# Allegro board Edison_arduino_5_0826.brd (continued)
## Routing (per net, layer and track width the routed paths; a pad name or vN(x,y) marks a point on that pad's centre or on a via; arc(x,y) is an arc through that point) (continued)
VBUS: length 8.6
  TOP w0.203: 20.96,17.02 21.3,16.67 J7.20
  TOP w0.3: Q10.3 103.02,18.64 ; Q10.2 103.02,19.59 ; CR1.2 v1(108.23,41.81)
  BOTTOM w0.3: TP18.1 16.83,20 v1(16.76,20.07)
  vias: v1(16.76,20.83) v1(114.45,16.66) v1(114.45,15.71)
VBUS_2: length 11.6
  TOP w0.3: R8.1 C9.2 110.49,9.01 110.76,8.74 U2.19
  TOP w0.33: 111.65,9.64 R8.1
  TOP w0.381: 117.49,5.24 116.41,5.22 115.22,6.41 115.22,8.53 114.11,9.64 111.65,9.64
VBUS_IN: length 5.9
  TOP w0.127: 108.74,20.09 108.12,20.09 R96.1 108.1,19.08
  TOP w0.381: CR8.2 113.98,19.2 ; CR8.2 113.18,18.58 ; CR8.2 112.38,19.2 ; J16.1 116.49,19.19 116.48,19.2
  TOP w0.5: 107.84,18.63 107.83,18.64 Q10.4
VBUS_OUT: length 3.9
  TOP w0.127: J6.1 C36.1 v1(111.03,44.22)
  TOP w0.25: U36.1 25.13,36.9 v1(24.92,37.11)
VIN: length 3.9
  PWR_GND w0.381: 73.63,60.12 J2A1.8 ; J2A1.8 74.6,59.16 ; J2A1.8 74.6,61.09 ; J2A1.8 75.57,60.12
  vias: v1(96.03,61.22) v1(96.05,60.35) v1(96.03,59.36) v1(96.05,58.46)
A0: length 55.7
  TOP w0.127: R52.2 61.35,46 62.36,47.01 62.36,54.74 66.19,58.57 67.97,58.57 J1A1.1 ; U15.A1 v1(62.5,40.76)
  BOTTOM w0.127: J1A1.1 69.22,60.43 TP64.1 70.87,63.12 70.87,51.74 71.02,51.59 71.02,49.81 70.13,48.92 69.24,48.92 68.2,47.88 64.49,47.88 61.75,45.14 61.75,43.91 62.5,43.16 v1(62.5,40.76)
A1: length 55.2
  TOP w0.127: J1A1.2 61.72,54.86 61.72,47.18 61.29,46.75 R53.2 ; U13.A1 v1(64.75,40.75)
  BOTTOM w0.127: J1A1.2 66.67,60.43 TP65.1 67.35,65.44 69.73,65.44 71.42,63.74 71.42,49.71 70.26,48.54 69.47,48.54 68.12,47.19 65.76,47.19 63.98,45.42 63.98,43.84 64.75,43.07 v1(64.75,40.75)
A2: length 55.4
  TOP w0.127: J1A1.3 61.03,56.72 R54.2 ; U11.A1 v1(67,40.76)
  BOTTOM w0.127: v1(67,40.76) 67,43.44 65.99,44.45 65.99,46 66.57,46.58 68.78,46.58 71.86,49.66 71.86,63.79 69.92,65.73 65.09,65.73 TP66.1 64.13,60.43 J1A1.3
A3: length 53.9
  TOP w0.127: R55.2 60.49,52.52 60.49,58.71 J1A1.4 ; U9.A1 v1(69.25,40.76)
  BOTTOM w0.127: J1A1.4 61.59,60.43 TP67.1 62.88,66.05 70.1,66.05 72.34,63.81 72.34,49.3 69.04,46 69.04,45.39 68.4,44.75 68.4,44.02 69.25,43.17 v1(69.25,40.76)
A4: length 106.7
  TOP w0.127: v1(72.75,34.29) 73.38,33.66 76.58,33.66 78.36,35.43 87.38,35.43 88.39,34.42 88.39,30.28 98.98,19.69 J2B1.9 ; R56.2 57.5,50.85 59.36,52.7 J1A1.5 ; U7.A1 v1(71.5,40.76)
  BOTTOM w0.127: J1A1.5 59.05,60.43 TP68.1 60.62,66.34 70.3,66.34 72.87,63.76 72.87,46.86 70.66,44.65 70.66,44.22 71.5,43.38 v1(71.5,40.76) 71.5,39.73 72.52,38.71 72.52,34.52 v1(72.75,34.29)
A5: length 109.3
  TOP w0.127: U5.A1 v1(73.75,40.76) ; v1(75.01,34.29) 76.53,35.81 87.53,35.81 88.77,34.57 88.77,30.53 101.52,17.78 J2B1.10 ; R57.2 56.75,51.16 58.42,52.83 58.42,58.52 J1A1.6
  BOTTOM w0.127: v1(75.01,34.29) 75.01,38.22 73.75,39.48 v1(73.75,40.76) 73.75,43.17 72.97,43.94 72.97,44.75 74.09,45.87 74.09,56.67 73.36,57.4 73.36,63.74 70.43,66.67 58.41,66.67 TP69.1 56.52,60.43 J1A1.6
AIN0: length 50
  TOP w0.127: U15.C2 63.63,38.62 63.63,37.47 64.9,36.2 87.63,36.2 89.15,34.67 89.15,30.77 90.93,29 99,29 100.71,30.71 100.71,34.29 100.53,34.47 R74.2
AIN1: length 43.6
  TOP w0.127: U13.C2 65.79,38.71 65.79,37.34 66.55,36.58 87.88,36.58 89.64,34.83 89.64,30.87 91.25,29.25 98,29.25 99.5,30.75 R75.2
AIN2: length 39.4
  TOP w0.127: R76.2 98,30.5 97.25,29.75 91.46,29.75 90.14,31.07 90.14,34.82 88,36.96 68.58,36.96 68.07,37.47 68.07,38.68 U11.C2
AIN3: length 35
  TOP w0.127: U9.C2 70.23,38.77 70.23,37.72 70.59,37.37 88.3,37.37 90.64,35.03 90.64,31.28 91.66,30.25 96,30.25 96.5,30.75 R77.2
AIN4: length 30.2
  TOP w0.127: U7.C2 72.52,38.73 72.52,38.23 73.03,37.72 88.65,37.72 91.14,35.24 91.14,31.49 91.87,30.75 94.5,30.75 95,31.25 R78.2
AIN5: length 25.4
  TOP w0.127: R79.2 93.5,31.5 93.25,31.25 92.32,31.25 91.64,31.94 91.64,35.44 88.6,38.48 76.27,38.48 75.5,39.25 U5.C2
AREF: length 67.7
  BOTTOM w0.127: J8.3 89.82,51.15 89.82,46.05 91.2,44.67 91.2,40.55 91.47,40.29 92.61,40.29 93.88,41.56 97.82,41.56 97.94,41.68 102.84,41.68 104.49,40.03 105.6,40.03 110.28,35.36 110.28,32.05 107.85,29.62 105.92,29.62 105.03,28.73 105.03,24 96.44,15.42 J2B1.8
DIG0: length 37.8
  TOP w0.127: J1B1.1 56.82,11.86 56.82,14.56 v1(57.09,14.83) 56.82,15.1 U33.C2 ; R64.2 76.84,26.75 v1(76.84,26.75)
  BOTTOM w0.127: J1B1.1 56.77,11.81 TP70.1 ; v1(57.09,14.83) 57.79,15.53 57.79,17.48 59.98,19.69 65.2,19.69 65.3,19.59 72.96,19.59 74.7,21.33 74.7,24.62 v1(76.84,26.75)
DIG1: length 34.8
  TOP w0.127: U31.C2 59.36,15.1 v1(59.63,14.83) 59.36,14.56 59.36,11.86 J1B1.2 ; R65.2 v1(77.35,26)
  BOTTOM w0.127: v1(59.63,14.83) 60.33,15.53 60.33,17.43 62.2,19.3 73.22,19.3 75.06,21.14 75.06,24.38 76.67,26 v1(77.35,26) ; J1B1.2 59.31,11.81 TP71.1
DIG2: length 31.8
  TOP w0.127: U29.C2 61.9,15.1 v1(62.17,14.83) 61.9,14.56 61.9,11.86 J1B1.3 ; R66.2 76.84,25.25 v1(76.84,25.25)
  BOTTOM w0.127: J1B1.3 61.85,11.81 TP72.1 ; v1(62.17,14.83) 62.87,15.53 62.87,17.65 64.13,18.92 73.38,18.92 75.44,20.99 75.44,23.85 v1(76.84,25.25)
DIG3: length 29.1
  TOP w0.127: U27.C2 64.44,15.1 v1(64.71,14.83) 64.44,14.56 64.44,11.86 J1B1.4 ; R67.2 v1(77.35,24.5)
  BOTTOM w0.127: v1(77.35,24.5) 76.7,24.5 75.82,23.62 75.82,20.83 73.53,18.54 66.04,18.54 65.28,17.78 65.28,15.4 v1(64.71,14.83) ; J1B1.4 64.52,11.79 TP73.1
DIG4: length 26
  TOP w0.127: U24.C2 66.98,15.1 v1(67.25,14.83) 66.98,14.56 66.98,11.86 J1B1.5 ; R68.2 76.84,23.75 v1(76.84,23.75)
  BOTTOM w0.127: v1(76.84,23.75) 76.84,20.7 74.3,18.16 68.83,18.16 67.94,17.27 67.94,15.53 v1(67.25,14.83) ; TP74.1 67.06,11.79 J1B1.5
DIG5: length 22.8
  TOP w0.127: R69.2 v1(77.35,23) ; U21.C2 69.52,15.1 v1(69.79,14.83) 69.52,14.56 69.52,11.86 J1B1.6
  BOTTOM w0.127: J1B1.6 69.6,11.79 TP75.1 ; v1(77.35,23) 77.35,20.71 74.42,17.78 70.87,17.78 70.36,17.27 70.36,15.4 v1(69.79,14.83)
DIG6: length 9.4
  TOP w0.127: J1B1.7 72.06,11.86 U19.C2 72.07,15.54 R70.2
  BOTTOM w0.127: TP76.1 72.01,11.81 J1B1.7
DIG7: length 9.6
  TOP w0.127: R71.2 75.53,15.53 U32.C2 74.6,11.86 J1B1.8
  BOTTOM w0.127: J1B1.8 74.55,11.81 TP77.1
DIG8: length 16.4
  TOP w0.127: J2B1.1 78.66,11.86 78.66,14.56 v1(78.93,14.83) 78.66,15.1 U30.C2 ; R58.2 82.5,20.52 v1(82.3,20.32)
  BOTTOM w0.127: v1(82.3,20.32) 79.63,17.65 79.63,15.53 v1(78.93,14.83) ; J2B1.1 78.61,11.81 TP78.1
DIG9: length 15.7
  TOP w0.127: R59.2 v1(83.25,20.35) ; U28.C2 81.2,15.1 v1(81.47,14.83) 81.2,14.56 81.2,11.86 J2B1.2
  BOTTOM w0.127: TP79.1 81.28,11.79 J2B1.2 ; v1(81.47,14.83) 82.04,15.4 82.04,19.14 v1(83.25,20.35)
DIG10: length 15.4
  TOP w0.127: J2B1.3 83.74,11.86 83.74,14.56 v1(84.01,14.83) 83.74,15.1 U26.C2 ; R60.2 84,20.52 v1(84.2,20.32)
  BOTTOM w0.127: v1(84.01,14.83) 84.58,15.4 84.58,19.94 v1(84.2,20.32) ; J2B1.3 83.82,11.79 TP80.1
DIG11: length 66.4
  TOP w0.127: R61.2 86.86,23.25 v1(87,23.11) 87,22.35 84.48,19.84 81.69,19.84 79.02,22.51 76.55,22.51 74.42,24.64 74.42,28.15 72.7,29.87 62.64,29.87 59.97,32.54 58.57,32.54 57.59,33.53 55.35,33.53 J4.4 ; U23.C2 86.28,15.1 v1(86.55,14.83) 86.28,14.56 86.28,11.86 J2B1.4
  BOTTOM w0.127: TP81.1 86.23,11.81 J2B1.4 ; v1(86.55,14.83) 86.55,15.56 87.15,16.16 87.15,17.05 88.42,18.32 88.42,18.57 88.8,18.95 90.58,18.95 90.96,19.33 90.96,21.24 89.08,23.11 v1(87,23.11)
DIG12: length 65.1
  TOP w0.127: U20.C2 88.82,15.1 v1(89.09,14.83) 88.82,14.56 88.82,11.86 J2B1.5 ; R62.2 v1(86.9,24) 87.12,24 87.63,23.5 87.63,22.61 84.61,19.59 81.56,19.59 78.89,22.25 76.17,22.25 73.91,24.51 73.91,27.81 72.14,29.59 62.54,29.59 59.95,32.18 J4.1
  BOTTOM w0.127: v1(86.9,24) 89.59,24 92.36,21.24 92.36,20.22 90.96,18.82 90.96,18.19 90.58,17.81 90.32,17.81 89.94,17.43 89.94,16.28 89.09,15.43 v1(89.09,14.83) ; J2B1.5 88.77,11.81 TP82.1
DIG13: length 67.6
  TOP w0.127: U18.C2 91.36,15.1 v1(91.63,14.83) 91.36,14.56 91.36,11.86 J2B1.6 ; R63.2 86.73,24.75 v1(86.87,24.89) 87.25,24.89 88.01,24.13 88.01,22.61 84.74,19.33 81.43,19.33 78.77,22 75.79,22 73.41,24.38 73.41,27.18 71.35,29.24 62.18,29.24 v1(59.8,31.61)
  BOTTOM w0.127: v1(59.8,31.61) J4.3 ; v1(86.87,24.89) 86.97,24.79 89.69,24.79 92.74,21.74 92.74,17.05 91.63,15.94 v1(91.63,14.83) ; J2B1.6 91.31,11.81 TP83.1
DIG13_1P8: length 65.8
  TOP w0.127: U43.A1 91.46,18.45 v1(91.47,18.44) 91.09,18.06 87.66,18.06 86.64,19.08 81.31,19.08 78.64,21.74 75.47,21.74 73.05,24.16 73.05,26.82 70.89,28.98 60.48,28.98 54.89,23.4 46.89,23.4 45.12,25.17 R87.1 ; U18.C1 90.33,15.53 v1(90.07,15.27)
  TOP w0.2: Q9.1 R87.1
  BOTTOM w0.127: v1(91.47,18.44) 91.47,18.32 90.96,17.81 90.96,15.9 90.32,15.27 v1(90.07,15.27)
FAULT: length 39.9
  TOP w0.127: J7.19 21.3,10 20.77,9.47 R36.1 20.14,9.47 20.02,9.34 20.02,8.48 v1(20.5,8) ; U36.3 25.82,32.93 v1(22.48,29.59)
  BOTTOM w0.127: v1(22.48,29.59) 14.82,21.94 14.82,17.9 15.94,16.79 15.94,13.94 20.5,9.38 20.5,8 v1(20.5,8) TP19.1
FW_RCVR: length 127
  TOP w0.127: SW1UI3.1 8.41,66.82 v1(8.41,65.81) ; v1(34,8) 32.98,9.02 32.51,9.02 31.3,10.23 J7.69
  BOTTOM w0.127: TP63.1 v1(34,8) 36,8 36.6,7.39 38.38,7.39 38.63,7.65 38.63,10.44 38.13,10.95 36.86,10.95 36.29,10.38 33.75,10.38 30.88,13.25 18.59,13.25 17.27,14.57 17.27,18.22 16.04,19.45 16.04,20.87 22,26.82 26.32,26.82 27.97,28.48 27.97,29.62 26.95,30.63 4.73,30.63 3.84,31.52 3.84,53.88 5.36,55.4 7.9,55.4 9.81,57.3 9.81,60.35 8.41,61.75 v1(8.41,65.81)
GP12_PWM0: length 43.7
  TOP w0.127: v1(32.64,9.78) 33.53,9.78 33.73,9.98 34.72,9.98 35.43,9.27 38.61,9.27 42.45,13.11 42.45,14.25 43.51,15.32 44.53,15.32 45.16,15.95 45.16,18.08 J12.2 ; J7.35 24.5,4 v1(23.5,3)
  BOTTOM w0.127: v1(32.64,9.78) 27.56,9.78 25.78,8 25.78,6.48 25.53,6.22 25.02,6.22 24.26,5.46 24.26,3.76 v1(23.5,3) TP34.1
GP13_PWM1: length 36.8
  TOP w0.127: J7.33 24.1,8.1 24,8 24,6 v1(23.5,5.5) ; J11.2 43.79,16.23 42.06,14.51 42.06,13.24 38.63,9.81 v1(36.73,9.81)
  BOTTOM w0.127: TP32.1 v1(23.5,5.5) 23.79,5.5 24.38,6.1 24.38,10.41 25.27,11.3 32.46,11.3 33.7,10.06 36.48,10.06 v1(36.73,9.81)
GP14: length 77.4
  TOP w0.127: J7.48 26.9,15.39 26.48,15.81 26.48,16.83 26,17.31 v1(26,19) ; U6.C1 72,44.21 v1(72.25,44.45)
  BOTTOM w0.127: v1(72.25,44.45) 72.07,44.28 72.07,41.33 72.25,41.15 72.25,40.28 73.6,38.93 73.6,33.59 73.18,33.17 71.91,33.17 68.23,29.49 61.24,29.49 56.29,24.54 44.1,24.54 41.43,21.87 34.19,21.87 33.55,22.51 33.55,23.52 32.79,24.28 25.94,24.28 25.17,23.52 25.17,20.98 26,20.16 TP41.1 v1(26,19)
GP15: length 79.2
  TOP w0.127: v1(27.55,46.85) 27.55,39.5 29.75,37.3 29.75,30.15 28.65,29.05 28.65,25.65 25.25,22.25 25.25,15.35 25.7,14.9 J7.42 ; v1(59.7,44.78) 59.7,44.7 59.8,44.7 59.8,44.8 60.55,44.8 63.6,47.85 63.65,47.85 R122.1 ; v1(54.3,44.4) 52.55,44.4 v1(52.25,44.7) 52.95,44.7 54.25,46 U17.22
  BOTTOM w0.127: v1(52.25,44.7) 50.9,46.05 TP88.1 32.25,46.05 31.45,46.85 v1(27.55,46.85) ; v1(54.3,44.4) 54.35,44.4 54.75,44.8 59.8,44.8 59.8,44.7 59.7,44.7 v1(59.7,44.78)
GP19: length 171.4
  TOP w0.127: R44.1 64.83,51.75 v1(64.9,51.82) 64.9,51.72 65.11,51.5 U16.19 ; J7.41 25.7,8.97 26.06,8.62 26.06,3.44 v1(26.5,3) 27.82,1.68 88.93,1.68 95.4,8.16 95.4,22.76 88.01,30.15 88.01,32.26 87.5,32.77 85.72,32.77 85.47,33.02 85.47,34.8 85.47,34.8 v1(85.47,34.93) ; v1(75.56,54.61) v1(69.85,54.61) ; v1(69.85,27.94) 69.47,27.56 68.96,27.56 68.75,27.35 U34.19
  BOTTOM w0.127: v1(69.85,27.94) 72.42,30.51 77.62,30.51 81.28,34.16 84.71,34.16 v1(85.47,34.93) 85.47,40.34 83.67,42.14 83.67,45.49 75.56,53.59 v1(75.56,54.61) ; v1(69.85,54.61) 68.45,54.61 65.66,51.82 v1(64.9,51.82) ; TP37.1 v1(26.5,3)
GP20: length 169.8
  TOP w0.127: v1(74.93,53.34) 74.04,54.23 70.74,54.23 v1(69.85,53.34) ; v1(68.71,27.94) 68.25,27.48 U34.20 ; U16.20 64.97,51 v1(64.9,50.93) 64.82,51 R43.1 ; J7.43 26.1,9.21 27,8.31 27,6 v1(26.5,5.5) 26.5,3.73 28.17,2.06 88.55,2.06 95.02,8.54 95.02,14.51 94.52,15.01 94.52,19.33 92.99,20.86 92.99,24.54 88.8,28.73 88.8,28.86 88.42,29.24 88.29,29.24 87.5,30.03 87.5,32 87.12,32.39 81.28,32.39 80.97,32.7 80.97,34.8 80.97,34.8 v1(80.97,34.93)
  BOTTOM w0.127: TP38.1 v1(26.5,5.5) ; v1(64.9,50.93) 65.53,50.93 68.35,53.75 69.44,53.75 v1(69.85,53.34) ; v1(68.71,27.94) 71.78,31.02 77.36,31.02 80.97,34.63 v1(80.97,34.93) 83.19,37.14 83.19,45.09 v1(74.93,53.34)
GP27: length 121.9
  TOP w0.127: v1(38.48,11.94) 38.48,24.51 v1(39.88,25.91) ; v1(28,3) 27.43,3.57 27.43,8.51 26.5,9.44 J7.45 ; Q3.2 77.5,51.03 R39.1 76.86,53.64 76.86,56.08 71.35,61.59 53.63,61.59 50.91,58.88 50.91,58.11 v1(51.36,57.66)
  BOTTOM w0.127: TP40.1 v1(28,3) 28.7,3.7 28.7,5.46 29.21,5.97 34.42,5.97 35.31,5.08 36.7,5.08 38.89,7.27 38.89,11.53 v1(38.48,11.94) ; v1(51.36,57.66) 50.4,56.7 50.4,52.6 51.56,51.44 51.56,46.54 53.85,44.25 53.85,44.2 53.85,44.2 53.85,43.6 53.95,43.5 53.95,42.9 53.85,42.8 53.85,40.6 53.85,40.6 53.85,40.48 51.56,38.19 51.56,33.2 45.44,27.08 41.05,27.08 v1(39.88,25.91)
GP28: length 113.1
  TOP w0.127: v1(51.52,58.62) 53.99,61.09 71.04,61.09 76.2,55.93 76.2,53.39 75.51,52.7 74.8,52.7 73.91,53.59 72.77,53.59 72.5,53.32 R40.1 72.5,51.03 Q4.2 ; v1(37.85,10.31) 37.85,24.89 v1(38.86,25.91) ; v1(28,8) 28,8.83 26.9,9.93 J7.47
  BOTTOM w0.127: v1(37.85,10.31) 37.85,9.65 37.24,9.04 29.04,9.04 v1(28,8) TP42.1 ; v1(38.86,25.91) 40.39,27.43 45.01,27.43 51.05,33.48 51.05,38.22 53.56,40.72 53.56,42.91 53.65,43 53.65,43.4 53.56,43.49 53.56,44.09 51.05,46.6 51.05,51.45 49.9,52.6 49.9,57.4 51.12,58.62 v1(51.52,58.62)
GP40: length 80.4
  TOP w0.127: J7.52 27.7,16.3 v1(27.5,16.5) ; v1(90.2,19.46) 90.45,19.72 U43.B2
  BOTTOM w0.127: TP44.1 v1(27.5,16.5) 28.1,15.9 32.03,15.9 33.3,17.17 38.76,17.17 45.11,23.52 56.67,23.52 59.84,20.35 64.92,20.35 65.43,19.84 72.67,19.84 74.45,21.62 74.45,25.05 76.61,27.21 77.24,27.21 81.69,22.76 83.34,22.76 87.15,18.95 87.53,18.95 88.04,19.46 v1(90.2,19.46)
GP41: length 106.3
  TOP w0.127: v1(95.28,27.84) 95.28,25.3 96.29,24.28 105.44,24.28 108.48,27.33 108.48,31.14 107.47,32.15 U40.B2 ; v1(27.5,19) 28.1,18.4 J7.54
  BOTTOM w0.127: v1(95.28,27.84) 87.91,27.84 85.88,25.81 83.97,25.81 82.83,26.95 80.93,26.95 80.04,27.84 76.48,27.84 73.81,25.17 73.81,22.12 73.05,21.36 60.86,21.36 58.19,24.03 44.6,24.03 41.22,20.65 27.76,20.65 27.5,20.39 TP46.1 v1(27.5,19)
GP42: length 85.6
  TOP w0.127: v1(26,21.5) 26.8,20.7 26.8,16 27.3,15.5 J7.50 ; v1(87.28,19.46) 87.78,19.46 88.04,19.72 U42.B2
  BOTTOM w0.127: TP43.1 v1(26,21.5) 26.57,20.93 26.57,18.69 27.08,18.19 39.4,18.19 44.98,23.78 57.56,23.78 60.48,20.86 73.31,20.86 74.2,21.74 74.2,25.17 76.48,27.46 77.37,27.46 81.81,23.01 83.72,23.01 v1(87.28,19.46)
GP43: length 109.1
  TOP w0.127: v1(29,19) 28.5,18.5 J7.56 ; v1(107.6,35.33) 107.47,35.2 U41.B2
  BOTTOM w0.127: TP48.1 v1(29,19) 28.91,19 28.35,18.44 27.33,18.44 26.93,18.85 26.93,20.63 27.33,21.03 41.1,21.03 44.35,24.28 58.7,24.28 61.24,21.74 72.67,21.74 73.31,22.38 73.31,25.05 80.93,32.67 89.31,32.67 91.72,35.08 91.72,39.14 92.1,39.52 97.44,39.52 97.69,39.27 101.37,39.27 102.26,38.38 106.67,38.38 108.21,36.84 108.21,35.94 v1(107.6,35.33)
GP44: length 71.8
  TOP w0.127: U14.C1 63,44.21 v1(63.25,44.45) ; v1(21.84,19.18) 22.1,18.92 J7.24
  BOTTOM w0.127: v1(63.25,44.45) 63.07,44.28 63.07,41.33 63.25,41.15 63.25,40.28 64.6,38.93 64.6,32.47 62.99,30.86 50.19,30.86 45.97,26.64 44.68,26.64 42.95,24.92 38.38,24.92 36.73,26.57 24.23,26.57 20.9,23.24 20.9,21.77 21.46,21.21 21.46,20.04 TP22.1 21.5,19.52 v1(21.84,19.18)
GP45: length 73.7
  TOP w0.127: v1(22.48,22.48) 22.48,20.52 22.5,20.5 J7.26 ; U12.C1 65.25,44.21 v1(65.5,44.45)
  BOTTOM w0.127: v1(22.48,22.48) 22.46,22.5 TP24.1 21.5,23.15 24.54,26.19 33.81,26.19 35.49,24.51 42.93,24.51 43.72,25.3 46.38,25.3 51.56,30.48 64.56,30.48 66.85,32.77 66.85,38.93 65.5,40.28 65.5,41.15 65.32,41.33 65.32,44.28 v1(65.5,44.45)
GP46: length 74.5
  TOP w0.127: v1(67.75,44.45) 67.5,44.21 U10.C1 ; J7.28 22.9,16.4 v1(23,16.5)
  BOTTOM w0.127: v1(67.75,44.45) 67.57,44.28 67.57,41.33 67.75,41.15 67.75,40.28 69.1,38.93 69.1,33.02 66.2,30.13 51.72,30.13 46.64,25.05 43.84,25.05 42.85,24.05 35.44,24.05 33.55,25.94 25.05,25.94 23.49,24.38 23.49,21.59 22.35,20.45 22.35,18.15 TP26.1 v1(23,16.5)
GP47: length 76.2
  TOP w0.127: v1(70,44.45) 69.75,44.21 U8.C1 ; J7.30 23.3,15.93 23.5,16.13 23.5,18.51 v1(23,19)
  BOTTOM w0.127: v1(70,44.45) 69.82,44.28 69.82,41.33 70,41.15 70,40.28 71.35,38.93 71.35,33.14 68.07,29.87 61.11,29.87 56.03,24.79 43.97,24.79 42.88,23.7 35.28,23.7 33.3,25.68 25.3,25.68 23.88,24.26 23.88,21.58 23,20.7 TP28.1 v1(23,19)
GP48: length 60.9
  TOP w0.127: J7.32 23.7,15.7 23.88,15.88 23.88,18.38 v1(24.5,19) ; v1(73.85,14.83) 74.09,15.07 U32.C1
  BOTTOM w0.127: TP29.1 v1(24.5,19) 25.27,18.23 25.27,16.51 26.54,15.24 33.15,15.24 33.81,15.9 41.63,15.9 42.04,15.49 46.86,15.49 49.02,13.34 72.77,13.34 73.85,14.41 v1(73.85,14.83)
GP49: length 60.2
  TOP w0.127: J7.34 24.1,15.74 24.13,15.77 24.13,16.13 v1(24.5,16.5) ; U30.C1 78.16,15.07 v1(77.91,14.83)
  BOTTOM w0.127: TP31.1 v1(24.5,16.5) 26.14,14.86 33.15,14.86 33.81,15.52 40.87,15.52 41.27,15.11 46.86,15.11 48.9,13.08 76.17,13.08 v1(77.91,14.83)
GP77: length 59.6
  TOP w0.127: J5.9 32.89,62.46 32.89,58.55 36.09,55.35 36.09,54.61 35.98,54.5 R45.2 ; R45.2 35.78,54.34 36.17,53.95 U35.A3 ; R45.2 35.78,54.89 35.69,54.99 34.16,54.99 33.78,54.61 33.78,50.17 29.6,45.98 29.6,39.59 30.65,38.54 30.65,29.85 30.5,29.7 v1(30.5,21.5) 29.96,20.96 29.96,18.91 29.59,18.54 29.59,16.13 29.3,15.84 J7.60
  BOTTOM w0.127: TP52.1 v1(30.5,21.5)
GP78: length 51.3
  TOP w0.127: v1(39.9,50.35) 39.9,52.75 v2(39.1,53.55) ; J7.58 28.9,16.4 v1(29,16.5) 29,18.33 29.59,18.92 29.59,29.19 30.35,29.95 30.35,37.65 29,39 29,46.15 v1(32.77,49.91)
  GND w0.127: v2(37.9,53.55) v2(39.1,53.55)
  BOTTOM w0.127: v1(39.9,50.35) 39.46,49.91 v1(32.77,49.91) ; TP50.1 v1(29,16.5)
GP79: length 46.4
  TOP w0.127: J7.62 29.7,15.6 29.97,15.88 29.97,18.47 v1(30.5,19) 30.5,20.72 31.12,21.34 31.12,38.94 30.08,39.98 30.08,45.45 v1(33.66,49.02) ; U35.C1 37.5,52.95 37.95,52.5 37.95,49.63 v1(37.34,49.02)
  BOTTOM w0.127: TP54.1 v1(30.5,19) ; v1(37.34,49.02) v1(33.66,49.02)
GP80: length 45.3
  TOP w0.127: U35.D1 37.9,52.95 38.25,52.6 38.25,49.3 v1(36.96,48.01) ; v1(34.54,48.01) 31.15,44.61 31.15,40.16 32,39.31 v1(32,21.5) 32,20.44 31.37,19.81 31.37,17.78 30.99,17.4 30.99,15.62 30.5,15.13 J7.66
  BOTTOM w0.127: TP58.1 v1(32,21.5) ; v1(36.96,48.01) v1(34.54,48.01)
GP81: length 45.1
  TOP w0.127: U35.E1 38.55,52.9 38.55,48.46 37.59,47.5 35.4,47.5 32,44.1 32,41.1 33.15,39.96 33.15,19.81 32.77,19.43 32.77,17.27 v1(32,16.5) 32,16.5 32,15.75 31.3,15.04 J7.70
  BOTTOM w0.127: TP62.1 v1(32,16.5)
GP82: length 43.2
  TOP w0.127: J7.64 30.1,15.22 30.5,15.62 v1(30.5,16.5) 30.5,17.67 31.12,18.29 31.12,20.57 31.5,20.96 31.5,39.1 30.65,39.95 30.65,44.84 36.32,50.51 36.32,52.2 36.7,52.57 U35.A1
  BOTTOM w0.127: TP56.1 v1(30.5,16.5)
GP83: length 43.7
  TOP w0.127: J7.68 30.9,15.03 31.37,15.49 31.37,17.15 32,17.78 v1(32,19) 32,19.55 32.64,20.19 32.64,39.58 31.61,40.61 31.61,44.31 37.65,50.35 37.65,52.4 37.1,52.95 U35.B1
  BOTTOM w0.127: TP60.1 v1(32,19)
GP84: length 51.2
  TOP w0.127: J7.44 26.1,15.35 25.55,15.9 25.55,22.05 27,23.5 27.05,23.5 29.1,25.55 29.1,29.1 30.05,30.05 30.05,37.4 28.5,38.95 28.5,46.9 v1(32.5,50.9) ; U35.E2 38.55,53.55 39.05,53.05 v1(39.05,51.25)
  BOTTOM w0.127: TP87.1 v1(39.05,51.25) 32.85,51.25 v1(32.5,50.9)
GP109: length 123.3
  TOP w0.127: U43.C2 90.2,20.22 89.94,20.47 v1(89.94,25.3) ; J7.55 28.5,9.89 29.5,8.89 v1(29.5,8) 29.5,6.44 29.97,5.97 29.97,4.95 29.08,4.06 29.08,3.3 29.34,3.05 30.23,3.05 30.73,3.56 31.75,3.56 32.26,3.05 71.37,3.05 72.9,4.57 89.15,4.57 92.48,7.9 92.48,12.85 92.86,13.24 v1(92.86,15.65) ; v1(100.33,37.47) 99.44,37.47 98.98,37 U3.17
  BOTTOM w0.127: TP49.1 v1(29.5,8) ; v1(100.33,37.47) 100.08,37.21 100.08,34.04 99.27,33.23 99.27,28.35 96.22,25.3 v1(89.94,25.3) 93.12,22.12 93.12,15.9 v1(92.86,15.65)
GP110: length 132.1
  TOP w0.127: U3.16 99.24,36.5 99.57,36.83 100.97,36.83 101.73,36.07 101.73,34.57 101.12,33.96 101.12,30.51 100.97,30.35 100.97,28.88 101.63,28.22 106.33,28.22 v1(106.83,28.73) ; J7.53 28.1,9.87 28.96,9.02 28.96,6.04 v1(29.5,5.5)
  BOTTOM w0.127: v1(29.5,5.5) TP47.1 30.19,3.81 36.09,3.81 38.79,6.5 53.21,6.5 55.91,3.81 104.01,3.81 109.9,9.69 109.9,13.28 110.74,14.12 110.74,25.71 107.72,28.73 v1(106.83,28.73)
GP111: length 111.4
  TOP w0.127: J7.51 27.7,9.64 28.57,8.76 28.57,6.08 v1(28,5.5) 28,4.19 28.6,3.58 28.6,2.95 29.11,2.44 71.66,2.44 72.8,3.58 89.18,3.58 92.86,7.27 92.86,12.35 93.75,13.24 v1(93.75,17.3) ; U40.C2 107.08,31.65 107.47,31.27 107.47,27.84 106.71,27.08 103.02,27.08 102.52,26.57 100.74,26.57 100.64,26.47 U44.1 99.18,25.17 v1(98.33,25.17)
  BOTTOM w0.127: v1(93.75,17.3) 98.33,21.87 v1(98.33,25.17) ; TP45.1 v1(28,5.5)
GP114: length 110.8
  TOP w0.127: 99.95,27.17 99.92,27.21 v1(99.34,27.21) ; U3.19 97.5,38.61 97.63,38.73 v1(99.7,38.73) ; J7.59 29.3,9.94 30.48,8.76 30.48,7.24 31,6.72 v1(31,5.5) 31,4.81 32.51,3.3 70.48,3.3 72.52,5.33 84.55,5.33 87.5,8.29 87.5,14.26 v1(88.07,14.83)
  BOTTOM w0.127: TP53.1 v1(31,5.5) ; v1(99.7,38.73) 100.84,37.59 100.84,36.58 100.46,36.2 100.46,33.91 99.7,33.15 99.7,27.56 v1(99.34,27.21) 98.83,26.7 98.83,20.66 92.01,13.84 89.06,13.84 v1(88.07,14.83)
GP115: length 144.2
  TOP w0.127: v1(29.59,3.56) 30.06,3.56 30.35,3.85 30.35,6.22 30.1,6.48 30.1,8.76 28.9,9.96 J7.57 ; U41.C2 107.73,34.7 108.36,35.33 v1(108.36,38.22) 106.8,39.78 105.56,39.78 102.52,39.78 100.71,37.97 99.31,37.97 98.84,37.5 U3.18
  BOTTOM w0.127: TP51.1 29.5,3.47 v1(29.59,3.56) 36.48,3.56 39.17,6.25 52.99,6.25 55.68,3.56 104.52,3.56 110.97,10 110.97,13.99 111,14.02 111,25.81 110.97,25.84 110.97,25.86 108.74,28.09 108.74,29.87 110.55,31.68 110.55,35.58 108.36,37.77 v1(108.36,38.22)
GP128: length 42.8
  TOP w0.127: U29.C1 60.71,14.84 60.71,11.68 59.63,10.6 55.05,10.6 49.28,4.83 33.66,4.83 33.27,5.21 33.27,7.23 v1(32.5,8) 30.5,10 J7.65
  BOTTOM w0.127: TP59.1 v1(32.5,8)
GP129: length 49.4
  TOP w0.127: U24.C1 65.79,14.84 65.79,11.18 64.52,9.91 55.12,9.91 49.4,4.19 33.4,4.19 32.5,5.09 v1(32.5,5.5) 32.5,6.49 31.62,7.37 31.62,8.38 30.1,9.9 J7.63
  BOTTOM w0.127: TP57.1 v1(32.5,5.5)
GP130: length 41.4
  TOP w0.127: J7.61 29.7,9.92 30.99,8.64 30.99,8.01 v1(31,8) 31,7.1 31.75,6.35 31.75,5.08 33.15,3.68 50.04,3.68 v1(55.24,8.89) ; U33.C1 55.24,14.46 v1(55.24,12.07)
  BOTTOM w0.127: v1(55.24,12.07) v1(55.24,8.89) ; TP55.1 v1(31,8)
GP131: length 45.9
  TOP w0.127: v1(58.61,14.83) 58.85,15.07 U31.C1 ; v1(26,16.5) 26,15.85 26.5,15.35 J7.46
  BOTTOM w0.127: v1(58.61,14.83) 58.13,14.35 53.72,14.35 52.07,16 52.07,19.1 48.03,23.14 45.37,23.14 39.14,16.92 33.43,16.92 32.16,15.65 26.85,15.65 v1(26,16.5) TP39.1
GP134: length 97.7
  TOP w0.127: R7.2 106.14,5.21 v1(102.87,5.21) ; v1(21.46,18.54) 21.7,18.3 J7.22
  BOTTOM w0.127: v1(102.87,5.21) 55.93,5.21 53.24,7.9 43.28,7.9 40.45,10.73 40.45,13.27 38.71,15.01 33.68,15.01 33.15,14.48 23.52,14.48 21.5,16.5 TP20.1 21.5,18.51 v1(21.46,18.54)
GP135: length 97.9
  TOP w0.127: R9.2 108.74,1.93 108.1,1.3 23.7,1.3 v1(22,3) 23,4 23,8.14 23.37,8.51 23.37,10.16 22.9,10.63 J7.27
  BOTTOM w0.127: TP27.1 v1(22,3)
GP165: length 99
  TOP w0.127: U4.C1 74.25,44.21 v1(74.5,44.45) ; J7.25 22.5,10.52 22.99,10.03 22.99,8.51 22.48,8 22.48,5.98 v1(22,5.5) ; v1(48.16,5.62) 51.21,8.66 51.21,18.06 v1(61.24,28.09)
  BOTTOM w0.127: v1(48.16,5.62) 43.72,1.17 20.22,1.17 19.84,1.55 19.84,3.2 20.35,3.71 21.11,3.71 21.9,4.5 TP25.1 v1(22,5.5) ; v1(61.24,28.09) 62,28.86 68.1,28.86 71.91,32.67 74.32,32.67 75.92,34.26 75.92,38.22 75.25,38.89 75.25,39.65 75.46,39.85 75.46,43.49 v1(74.5,44.45)
GP182_PWM2: length 29.4
  TOP w0.127: v1(25,8) 24.9,8.1 J7.37 ; v1(34.16,9.53) 34.8,8.89 38.73,8.89 42.93,13.08 45.24,13.08 J12.4
  BOTTOM w0.127: TP35.1 v1(25,8) 27.31,10.31 32.79,10.31 33.58,9.53 v1(34.16,9.53)
GP183_PWM3: length 33.4
  TOP w0.127: v1(25,3) 25.5,3.5 25.5,8.66 25.3,8.86 J7.39 ; J11.4 37.87,5.72 v1(35.56,5.72)
  BOTTOM w0.127: v1(35.56,5.72) 35,6.27 26.59,6.27 25.78,5.46 25.78,3.78 v1(25,3) TP36.1
GPI_PWRBTN_N: length 90.4
  TOP w0.127: J7.17 20.9,10.18 20.57,9.86 20.14,9.86 19.76,9.47 19.76,6.24 v1(20.5,5.5)
  TOP w0.3: R49.1 v1(13.75,66.71)
  BOTTOM w0.127: TP17.1 v1(20.5,5.5) 20.03,5.97 16.34,5.97 15.11,7.2 15.11,16.52 2.03,29.59 2.03,65.15 3.59,66.71 v1(13.75,66.71)
GPI_PWRBTN_N_L: length 5.6
  TOP w0.3: R48.2 18.62,68.41 SW1UI2.1 15.87,68.03 R49.2
MSIC_SLPCLK_2: length 9
  TOP w0.127: v1(16.13,8.26) 16.51,8.64 17.07,8.64 18.9,10.47 J7.7
  BOTTOM w0.127: TP8.1 19,8.18 18.47,8.71 16.59,8.71 v1(16.13,8.26)
OSC_CLK_OUT_0: length 8.2
  TOP w0.127: J7.67 30.9,10.12 32.38,8.64 32.64,8.64 34,7.28 v1(34,5.5)
  BOTTOM w0.127: TP61.1 v1(34,5.5)
PSW: length 55.1
  TOP w0.127: J7.21 21.7,9.49 R37.1 21.89,9.48 22.1,9.27 22.1,8.64 21.46,8 21.46,3.96 v1(20.5,3) ; U36.4 27.68,32.63 v1(22.61,27.56)
  BOTTOM w0.127: v1(22.61,27.56) 22.37,27.56 15.79,20.97 15.79,19 16.99,17.8 16.99,14.35 18.37,12.97 20.18,12.97 24.13,9.02 24.13,6.35 23.88,6.1 23.24,6.1 22.73,5.59 22.73,3.94 22.25,3.46 20.96,3.46 v1(20.5,3) TP21.1
PWM0_OUT: length 24.9
  TOP w0.127: v1(63.69,14.83) 63.93,15.07 U27.C1 62.96,15.53 R91.1
  BOTTOM w0.127: v1(63.69,14.83) 62.96,14.1 52.96,14.1 51.18,15.88 51.18,19.3 48.69,21.79 J12.1
PWM1_OUT: length 29.7
  TOP w0.127: v1(68.77,14.83) 69.01,15.07 U21.C1 68.06,15.53 R90.1
  BOTTOM w0.127: J11.1 45.01,18.03 47.75,18.03 51.94,13.84 67.79,13.84 v1(68.77,14.83)
PWM2_OUT: length 28.8
  TOP w0.127: R89.1 70.6,15.53 U19.C1 71.55,15.07 v1(71.31,14.83)
  BOTTOM w0.127: v1(71.31,14.83) 70.07,13.59 49.45,13.59 J12.3
PWM3_OUT: length 40.1
  TOP w0.127: v1(80.45,14.83) 80.7,15.07 U28.C1 79.72,15.53 R92.1
  BOTTOM w0.127: v1(80.45,14.83) 78.45,12.83 45.14,12.83 J11.3
PWM4_OUT: length 79.8
  TOP w0.127: v1(101.98,29.54) 101.98,30.98 R94.1 101.98,31.42 101.98,32.23 102.75,33
  BOTTOM w0.127: v1(101.98,29.54) 102.77,28.75 102.77,23.01 92.39,12.63 92.39,6.86 91.75,6.22 56.31,6.22 50.9,11.63 J12.5
PWM5_OUT: length 93.5
  TOP w0.127: U22.B2 102.33,36.83 v1(101.6,36.83) 101.6,36.6 102,36.2 102,35.9 102.2,35.7 R93.1
  BOTTOM w0.127: J11.5 52.68,9.09 56.06,5.72 91.95,5.72 95,8.76 95,14.6 104.52,24.13 104.52,28.98 106.96,31.42 106.96,33.94 104.58,36.32 104.52,36.32 104.01,36.83 v1(101.6,36.83)
RCVR_MODE: length 85.6
  TOP w0.127: J7.31 23.7,8.2 v1(23.5,8) ; SW1UI4.1 6.01,68.41 6.6,67.82 6.6,65.79 v1(6.99,65.41)
  BOTTOM w0.127: TP30.1 v1(23.5,8) 21.72,8 21.21,7.49 21.21,6.6 20.96,6.35 16.55,6.35 15.42,7.48 15.42,16.69 5.33,26.77 5.33,28.45 2.92,30.86 2.92,63.12 5.21,65.41 v1(6.99,65.41)
RESETOUT#: length 64.4
  TOP w0.127: J7.36 24.5,15.61 24.95,16.06 24.95,21.05 v1(24.5,21.5) ; Q8.1 36.53,38.83 36.4,38.95 34.05,38.95 33.65,39.35 33.65,40.25 32.5,41.4 32.5,43.85 35.3,46.65 v1(35.65,46.65) ; R123.2 29.68,53.8 30.55,53.8 31.55,52.8 v1(31.55,51.05)
  TOP w0.2: v1(34.11,22.63) 34.11,36.14 34.67,36.7 R85.1 Q8.1
  BOTTOM w0.127: v1(31.55,51.05) 31.55,48.3 33.2,46.65 v1(35.65,46.65)
  BOTTOM w0.2: v1(24.5,21.5) TP33.1 24.5,23.99 25.81,25.3 32.92,25.3 34.11,24.11 v1(34.11,22.63)
SD_CLK: length 16.6
  TOP w0.127: J5.5 38.33,67.24 37.67,66.57 v2(37.67,54.76)
  GND w0.127: v2(37.67,54.76) 37.9,54.53 v2(37.9,53.95)
SD_CMD: length 16.4
  TOP w0.127: U35.C4 37.5,54.42 37.29,54.64 37.29,66.8 36.13,67.96 J5.3
SD_DAT0: length 16.9
  TOP w0.127: U35.D4 38,54.45 38,65.94 40.53,68.47 J5.7
SD_DAT1: length 17.2
  TOP w0.127: U35.E4 38.3,65.25 41.58,68.53 J5.8
SD_DAT2: length 17
  TOP w0.127: U35.A4 36.7,66.07 33.93,68.83 J5.1
SD_DAT3: length 16.7
  TOP w0.127: U35.B4 36.98,54.47 36.98,66.4 35.03,68.34 J5.2
SHLD_RESET: length 113.3
  TOP w0.25: U17.8 v1(59.71,45.5)
  TOP w0.3: U17.17 56.25,48.84 55.5,49.59 v1(55.5,50.48)
  TOP w0.33: J4.5 55.5,38.45 54.53,38.45 54.2,38.78 R19.1 53.95,39.25 53.95,39.26 C34.1
  TOP w0.5: SW1UI1.1 v1(22.5,66.7) ; v1(55.5,50.48) 55.31,50.67 51.69,50.67 50.29,52.07 50.29,59.29 51.63,60.63 51.63,60.65 53.47,62.48 v1(53.49,62.48) 82.4,62.48 v1(82.42,62.46)
  BOTTOM w0.5: 59.72,45.51 59.77,45.45 59.85,45.45 59.89,45.41 60,45.41 60.5,44.91 60.5,41.07 J4.5 ; 59.72,45.51 v1(59.71,45.5) ; 59.72,45.51 59.72,47.79 57.4,50.1 55.88,50.1 v1(55.5,50.48) ; v1(82.42,62.46) 86.26,62.46 87.3,61.42 J2A1.3 ; v1(22.5,66.7) 46.46,66.7 50.67,62.48 v1(53.49,62.48)
SPI_CLK_SEL: length 62.8
  TOP w0.127: U16.13 69,52.97 v1(68.99,52.99) ; v1(61.75,32.92) 62.13,32.54 62.77,32.54 64.92,30.38 85.88,30.38 90.45,25.81 90.45,21.23 U43.D2
  BOTTOM w0.127: v1(61.75,32.92) 61.75,35.84 61,36.59 61,45.51 64.29,48.8 65.69,48.8 66.45,49.56 66.45,51.34 68.1,52.99 v1(68.99,52.99)
SPI_FS_SEL: length 57.9
  TOP w0.127: v1(106.7,30.13) U40.D2 ; v1(108.99,35.21) 108.99,40.13 108.71,40.41 99.72,40.41 98.96,41.18 84.1,41.18 83.09,40.16 79.68,40.16 74.35,45.49 73.05,45.49 71.91,46.64 71.91,48.92 70.64,50.19 70.51,50.19 70.2,50.5 U16.10
  BOTTOM w0.127: v1(106.7,30.13) 106.83,30.13 108.36,31.65 108.36,34.57 v1(108.99,35.21)
SPI_RXD_SEL: length 62.7
  TOP w0.127: v1(70.39,51.97) 69.91,51.5 U16.12 ; v1(62,31.65) 63.53,30.13 85.5,30.13 88.8,26.82 88.8,22.38 88.55,22.13 U42.D2
  BOTTOM w0.127: v1(62,31.65) 62,32.16 62.38,32.54 62.38,36.48 61.4,37.46 61.4,45.4 64.29,48.29 67.97,48.29 69.24,49.56 69.24,50.83 v1(70.39,51.97)
SPI_TXD_SEL: length 55.2
  TOP w0.127: U41.D2 108.88,34.2 109.61,34.93 109.61,40.02 108.41,41.22 99.42,41.22 99.21,41.43 83.85,41.43 82.96,40.54 79.72,40.54 74.47,45.79 73.26,45.79 72.34,46.72 72.34,49.64 70.97,51 U16.11
TRI_STATE_ALL: length 45.2
  TOP w0.127: Q7.5 R35.2 82.03,43.32 v1(82.05,43.3)
  TOP w0.3: U17.16 v1(56.75,49.07)
  PWR_GND w0.127: v1(56.75,49.07) 55.8,48.12 55.8,47.19 55.82,47.17 55.82,44.64 56.26,44.2 56.26,43.15 56.7,42.71 56.7,41.55 61.4,36.85 80.35,36.85 83.6,40.1 83.6,42.35 82.65,43.3 v1(82.05,43.3)
USB_DN: length 133.9
  TOP w0.112: 116.36,29.63 v1(116.36,29.62) ; 116.36,29.63 116.36,30.02 116.25,30.13 115.99,30.13 115.61,30.52 115.49,30.52 115.36,30.39 EU1.7 ; 116.36,29.63 116.87,30.14 118.04,30.14 118.15,30.03 118.15,28.07 117.02,26.94 110.32,26.94 109.6,26.22 109.6,25.96 v1(109.32,25.68) ; J7.18 20.9,14.88 20.83,14.95 20.83,15.62 v1(19.81,16.64)
  BOTTOM w0.112: v1(109.32,25.68) 109.6,25.4 109.6,15.27 109.26,14.93 109.26,10.71 103.12,4.57 56.02,4.57 53.34,7.25 43.31,7.25 39.75,10.81 39.75,12.95 37.96,14.74 33.92,14.74 33.02,13.84 22.99,13.84 20.74,16.09 19.6,16.09 19.49,16.2 19.49,16.31 v1(19.81,16.64)
USB_DP: length 135.7
  TOP w0.112: J7.16 20.5,14.88 20.59,14.97 20.59,15.52 19.98,16.13 19.43,16.13 v1(18.92,16.64) ; EU1.8 115.36,30.89 115.49,30.76 115.7,30.76 116.09,30.37 116.25,30.37 116.36,30.48 v1(116.36,30.89) 116.87,30.38 118.14,30.38 118.39,30.13 118.39,27.97 117.12,26.7 110.42,26.7 109.84,26.12 109.84,25.96 v1(110.12,25.68)
  BOTTOM w0.112: v1(110.12,25.68) 109.84,25.4 109.84,15.17 109.5,14.83 109.5,10.61 103.22,4.33 55.92,4.33 53.24,7.01 43.21,7.01 39.51,10.71 39.51,12.86 37.86,14.51 34.02,14.51 33.12,13.6 22.89,13.6 20.64,15.85 19.5,15.85 19.25,16.1 19.25,16.31 v1(18.92,16.64)
USB_ID: length 148.9
  TOP w0.127: v1(112.04,1.4) 111.56,0.92 108.41,0.92 108.41,0.92 20.93,0.92 19.81,2.03 19.81,3.56 19,4.37 v1(19,5.5) 17.16,5.5 15.62,7.04 15.62,8.89 16.19,9.46 17.08,9.46 17.35,9.73 17.35,10.31 17.55,10.52 17.97,10.52 18.1,10.64 J7.3 ; v1(110.85,37.36) Q11.3
  BOTTOM w0.127: v1(112.04,1.4) 112.04,9.77 111.27,10.54 111.27,25.94 108.99,28.22 108.99,29.49 110.85,31.35 110.85,37.36 v1(110.85,37.36) ; TP4.1 v1(19,5.5)
USBA_CONN_DN: length 23.6
  TOP w0.112: EU1.2 111.26,31.39 111.13,31.52 110.87,31.52 110.41,31.99 110.41,33.41 110.01,33.8 110.01,40.12 112.7,42.81 114.99,42.81 116.12,43.94 116.12,47.17 115.75,47.54 114.76,47.54 J6.2
USBA_CONN_DP: length 23.6
  TOP w0.112: EU1.1 111.26,31.89 111.13,31.76 110.97,31.76 110.64,32.09 110.64,33.51 110.25,33.9 110.25,40.02 112.8,42.57 115.09,42.57 116.36,43.84 116.36,47.27 115.85,47.78 114.84,47.78 113.95,48.67 J6.3
V_1P80: length 116.2
  TOP w0.2: v1(107.47,36.22) 106.95,35.7 U41.A2 ; U42.A2 88.55,19.08 88.17,18.7 v1(87.91,18.7) ; U43.A2 90.45,18.7 90.45,18.51 v1(90.44,18.51) ; U44.6 99.5,26.47 v1(99.34,26.32) ; 107.61,32.65 U40.A2
  TOP w0.23: v1(66.21,17.23) 66.47,16.96 U24.A1 ; U26.A1 83.24,16.96 v1(82.97,17.23) ; 62.76,16.26 63.04,16.53 U27.A1 63.93,16.96 v1(63.67,17.23) ; v1(85.51,17.23) 85.78,16.96 U23.A1 ; U33.A1 56.31,16.96 v1(56.05,17.23) ; v1(80.43,17.23) 80.7,16.96 U28.A1 79.8,16.53 79.53,16.26 ; C31.2 36.33,53.55 U35.A2 ; v1(102.5,36.05) 102.75,36.3 U22.A2 ; C15.2 74.25,42.03 U4.A1 ; U29.A1 61.39,16.96 v1(61.13,17.23) ; v1(73.83,17.23) 74.09,16.96 U32.A1 ; U31.A1 58.85,16.96 v1(58.59,17.23) ; v1(90.45,17.05) 90.63,17.05 90.86,16.82 U18.A1 ; v1(102.5,31.8) 102.75,32.05 102.75,32.5 ; v1(77.89,17.23) 78.16,16.96 U30.A1 ; C19.2 65.25,42.03 U12.A1 ; U14.A1 63,42.03 C20.2 ; 67.87,16.26 68.14,16.53 U21.A1 69.01,16.96 v1(68.75,17.23) ; v1(87.78,16.92) 87.93,16.92 U20.A1 ; v1(71.29,17.23) 71.55,16.96 U19.A1 70.68,16.53 70.41,16.26 ; C16.2 72,42.03 U6.A1 ; C18.2 67.5,42.03 U10.A1 ; U8.A1 69.75,42.03 C17.2
  TOP w0.25: R85.2 33.84,38.35 v1(33.81,38.38)
  TOP w0.3: U3.21 C14.2 96.97,39.47 C13.1 v1(97.86,39.75) ; R45.1 v1(34.63,54.5) ; U2.1 108.26,2.94 C10.2 102.92,2.67 97.82,7.77 v1(97.82,14.25) ; v1(44.48,28.48) 44.5,28.45 R87.2 ; R46.1 v1(40.62,54) ; C19.2 v1(65.9,42) ; Q3.1 78.03,52.47 R39.2 v1(78.57,53) ; R36.2 20.88,8.94 v1(21.08,9.14) ; C15.2 v1(74.9,42) ; v1(63.22,53.55) C22.2 ; C16.2 v1(72.65,42) ; R94.2 102.73,31.57 v1(102.5,31.8) ; v1(109.63,33.43) 108.85,32.65 107.61,32.65 ; C20.2 v1(63.65,42) ; R43.2 v1(63.1,51) ; C31.2 v1(35.78,52.39) ; C18.2 v1(68.15,42) ; R47.2 11.29,61.97 v1(11.3,61.98) ; Q13.4 26.9,52.04 R102.1 v1(28.46,52.85) ; v1(63.15,51.75) R44.2 ; v1(102.5,36.05) 102.73,35.82 R93.2 ; v1(73.62,53) R40.2 73.03,52.47 Q4.1 ; C17.2 v1(70.4,42)
  TOP w0.5: R82.1 20.81,38.64 J15.2 ; Q6.1 87.5,34.42 v1(87,34.93) ; Q5.1 83,34.74 v1(83.19,34.93)
  PWR_GND w0.381: 19.09,39.45 J15.2 ; J15.2 20,40.36 ; J15.2 20.91,39.45 ; J15.2 20,38.54
  BOTTOM w0.3: TP11.1 J15.2
  BOTTOM w0.5: v1(26.67,29.21) 26.16,28.7 22.61,28.7 15.3,21.4 15.3,18.14 16.42,17.02 16.42,14.14 21.08,9.48 v1(21.08,9.14)
V_1P80_IO: length 7.1
  TOP w0.127: R122.2 64.17,49.11 C21.2
  TOP w0.25: U34.23 v1(66.75,27.84) ; U34.18 v1(70.32,26.25) ; C21.2 v1(64.92,50.06) ; U34.21 v1(67.75,27.84)
  TOP w0.3: U16.21 65.23,50.5 64.92,50.19 v1(64.92,50.06) 64.92,49.68 65.11,49.5 U16.23
  vias: v1(21.74,52.1) v1(22.51,52.1)
V_3P30: length 16.2
  TOP w0.25: v1(116.36,32.29) 115.96,31.89 EU1.10
  TOP w0.3: J14.2 14.56,38.64 R83.1
  BOTTOM w0.381: 12.84,39.45 J14.2 ; J14.2 14.66,39.45 ; J14.2 13.75,38.54 ; J14.2 13.75,40.36 ; J2A1.4 84.76,61.09 ; J2A1.4 85.73,60.12 ; J2A1.4 83.79,60.12 ; J2A1.4 84.76,59.16 ; J9.3 85,54.8 ; J9.3 84.03,53.83 ; J9.3 85.97,53.83 ; J9.3 85,52.86
V_SHIELD: length 29.1
  TOP w0.225: 54.67,40.08 54.55,40.2 R114.2
  TOP w0.23: U5.A2 74.25,41.26 C25.2 ; C24.2 65.25,41.26 U13.A2 ; U9.A2 69.75,41.26 C30.2 ; C23.2 63,41.26 U15.A2 ; U7.A2 72,41.26 C29.2 ; C28.2 67.5,41.26 U11.A2
  TOP w0.25: R100.1 28.46,48.78 v1(28.48,48.8)
  TOP w0.3: R34.1 v1(80.73,42) ; R41.2 v1(79.65,47) ; v1(75,40.56) 75,40.87 74.58,41.3 C25.2 ; v1(68.25,40.56) 68.25,40.87 67.83,41.3 C28.2 ; v1(72.75,40.56) 72.75,40.87 72.33,41.3 C29.2 ; R42.2 v1(75.34,47) ; 55.09,40.57 55.09,40.57 R114.2 ; R100.1 26.9,47.97 26.21,47.97 ; v1(70.5,40.56) 70.5,40.87 70.08,41.3 C30.2 ; v1(63.75,40.56) 63.75,40.87 63.33,41.3 C23.2 ; 54.63,39.78 R19.2 ; R12.1 v1(80.72,42.75) ; v1(66,40.56) 66,40.87 65.58,41.3 C24.2 ; Q7.4 v1(82.05,44.7)
  TOP w0.381: J9.2 85,52.26 ; J9.2 84.03,51.29 ; J9.2 85.97,51.29 ; 91.53,48.75 J8.1 ; J8.1 92.5,49.72 ; J8.1 92.5,47.78 ; J8.1 93.47,48.75
  vias: v1(60.15,35.68) v1(60.15,34.85) v1(60.16,34) v1(76.2,33.02) v1(76.58,40.39) v1(76.86,34.95) v1(77.5,33.3) v1(77.85,40.39) v1(77.85,39.12) v1(78,34.19) v1(78.64,33.3) v1(78.74,34.93) v1(79.63,34.42)
V_SHIELD_SW: length 17.3
  TOP w0.23: U23.A2 86.28,16.98 v1(86.53,17.23) ; U19.A2 72.06,16.98 v1(72.3,17.23) ; v1(89.05,17.05) 89.05,17.05 88.82,16.82 U20.A2 ; U27.A2 64.44,16.98 v1(64.68,17.23) ; U28.A2 81.2,16.98 v1(81.45,17.23) ; v1(57.06,17.23) 56.82,16.98 U33.A2 ; U10.A2 v1(66.48,42.75) ; U21.A2 69.52,16.98 v1(69.76,17.23) ; U6.A2 v1(70.98,42.75) ; v1(78.91,17.23) 78.66,16.98 U30.A2 ; U14.A2 v1(61.98,42.75) ; U8.A2 v1(68.73,42.75) ; U31.A2 59.36,16.98 v1(59.6,17.23) ; U26.A2 83.74,16.98 v1(83.99,17.23) ; U12.A2 v1(64.23,42.75) ; U29.A2 61.9,16.98 v1(62.14,17.23) ; U18.A2 91.36,16.98 v1(91.61,17.23) ; U4.A2 v1(73.23,42.75) ; v1(67.22,17.23) 66.98,16.98 U24.A2 ; v1(74.84,17.23) 74.6,16.98 U32.A2
  TOP w0.3: Q7.3 v1(87,44.7) ; Q7.2 v1(86.93,43.75) 87.54,43.75 R125.2
V_SHLD_IO: length 21.4
  TOP w0.127: v1(82.2,28.48) 82.2,28.47 C27.2 U39.21 ; 53.3,43.1 v1(53.2,43.2) ; v1(85.24,26.32) 85.18,26.25 U39.18
  TOP w0.25: v1(53.24,45.75) 53.53,46.04 C26.2
  TOP w0.3: U17.21 C26.2 ; R121.2 60.73,43.97 60.5,44.2 59.2,44.2 v1(59.15,44.25)
  TOP w0.33: R50.2 83.5,29.25 v1(83.2,29.55) ; R117.2 R116.2 53.3,43.1 ; R51.2 84.42,29.03 v1(84.75,29.36) ; R121.2 R120.2 R119.2 R118.2
  BOTTOM w0.127: v1(85.24,26.32) 84.36,26.32 v1(82.2,28.48)
  BOTTOM w0.225: v1(54.6,43.8) v1(55.05,44.25)
  BOTTOM w0.3: v1(55.05,44.25) v1(59.15,44.25)
  vias: v1(21.74,48.03) v1(22.51,48.03)
V_SYS: length 43.1
  TOP w0.2: v1(44.1,30.76) 44.96,29.9 R88.2
  TOP w0.25: C5.1 43.25,32.5 U38.11 ; v1(46.38,30.76) 46.89,31.27 R113.2
  TOP w0.3: C32.2 37,52.24 v1(37.08,52.32) ; R105.1 19.46,58.71 20.7,59.95 v1(21.8,59.95) ; R104.1 v1(27.28,55.85) Q14.4 ; R86.2 34.2,39.86 v1(34.19,39.85) ; R48.1 19,63.04 20.96,61.09 v1(22.99,61.09) ; v1(43.88,32.5) C5.1
  GND w0.3: v2(37.1,53.55) 37.08,53.53 v1(37.08,52.32)
  BOTTOM w0.3: 21.75,33.15 21.7,33.1 12.6,33.1 9.4,36.3 9.4,41.55 8,42.95 TP3.1
V_SYSTEM: length 9.5
  TOP w0.127: C49.2 R106.1 23.61,56.78 Q14.2 Q14.3
  TOP w0.3: J10.2 8.31,38.64 R84.1
  TOP w0.381: 7.5,38.54 J10.2 ; J10.2 8.41,39.45 ; J10.2 7.5,40.36 ; J10.2 6.59,39.45
V_VBAT_BKUP: length 6.2
  TOP w0.203: v1(21.97,6.22) 21.97,7.97 22.48,8.48 22.48,9.78 22.1,10.16 J7.23
  BOTTOM w0.3: TP23.1 22,6.25 v1(21.97,6.22)
N11374: length 11.4
  TOP w0.112: 114.71,5.25 115.34,4.62 118.31,4.62 118.68,4.99 118.68,5.96 118.57,6.07 118.46,6.07 118.25,5.87 J3.2 ; 114.71,5.25 v1(114.71,5.27) ; 114.71,5.25 114.71,4.86 114.6,4.75 114.26,4.75 113.82,5.19 113.82,6.74 113.57,6.99 112.93,6.99 112.8,7.12 U2.15
N11378: length 12.1
  TOP w0.112: J3.3 118.25,6.52 118.46,6.31 118.67,6.31 118.92,6.06 118.92,4.89 118.41,4.38 115.09,4.38 v1(114.71,4) 114.71,4.4 114.6,4.51 114.16,4.51 113.58,5.09 113.58,6.64 113.47,6.75 112.93,6.75 112.8,6.62 U2.14
N30036849: length 0.9
  TOP w0.127: R8.2 111.26,9.09 U2.18
N30040341: length 25.5
  TOP w0.127: J5.4 37.23,71.02 37.11,71.15 33.4,71.15 33.05,70.79 33.05,68.5 36.42,65.13 36.42,54.58 36.3,54.46 v2(36.3,54.31)
  GND w0.127: v2(37.1,53.95) 36.78,53.95 36.58,53.75 v2(35.78,53.75) 35.78,54.18 35.91,54.31 v2(36.3,54.31)
N30044742: length 1.2
  TOP w0.127: U35.E3 39.42,53.95 R46.2
N30057553: length 1.7
  TOP w0.3: U3.4 93.62,36 93.6,36.02 93.6,36.32 93.78,36.5 U3.3
N30057571: length 1.5
  TOP w0.3: U3.5 R10.2
N30057573: length 1.2
  TOP w0.3: U3.23 R11.2
N30057609: length 1.2
  TOP w0.3: v1(99.31,35.31) 99.12,35.5 U3.14
  vias: v1(92.71,38.1) v1(93.34,38.73) v1(93.98,38.1)
N30058254: length 7.1
  TOP w0.127: v1(63.52,39.37) 63.14,39.75 U15.B2 ; U14.C2 62.5,44.18 v1(62.23,44.45)
  BOTTOM w0.127: v1(63.52,39.37) 62.97,39.92 62.97,41.07 62.76,41.28 62.76,43.92 v1(62.23,44.45)
N30058257: length 7.1
  TOP w0.127: v1(64.48,44.45) 64.75,44.18 U12.C2 ; v1(65.77,39.37) 65.39,39.75 U13.B2
  BOTTOM w0.127: v1(64.48,44.45) 65.01,43.92 65.01,41.28 65.22,41.07 65.22,39.92 v1(65.77,39.37)
N30058260: length 7.1
  TOP w0.127: v1(66.73,44.45) 67,44.18 U10.C2 ; v1(68.02,39.37) 67.64,39.75 U11.B2
  BOTTOM w0.127: v1(68.02,39.37) 67.47,39.92 67.47,41.07 67.26,41.28 67.26,43.92 v1(66.73,44.45)
N30058263: length 7.1
  TOP w0.127: v1(68.98,44.45) 69.25,44.18 U8.C2 ; v1(70.27,39.37) 69.89,39.75 U9.B2
  BOTTOM w0.127: v1(70.27,39.37) 69.72,39.92 69.72,41.07 69.51,41.28 69.51,43.92 v1(68.98,44.45)
N30058266: length 12.5
  TOP w0.127: U7.B2 72.14,39.75 v1(72.52,39.37) ; v1(71.23,44.45) 71.5,44.18 U6.C2 ; Q4.3 73.5,48.7 R42.1 v1(73.5,46.39)
  BOTTOM w0.127: v1(72.52,39.37) 71.97,39.92 71.97,41.07 71.76,41.28 71.76,43.92 v1(71.23,44.45) 73.17,46.39 v1(73.5,46.39)
N30058269: length 16.4
  TOP w0.127: v1(77.24,48.67) 77.29,48.71 Q3.3 78.5,48.7 R41.1 ; v1(73.48,44.45) 73.75,44.18 U4.C2 ; U5.B2 v1(74.76,39.75)
  BOTTOM w0.127: v1(74.76,39.75) 74.4,40.12 74.4,40.89 74.01,41.28 74.01,43.92 v1(73.48,44.45) 74.58,45.55 74.58,47.78 75.47,48.67 v1(77.24,48.67)
N30061760: length 21
  TOP w0.127: v1(62.93,33.85) 62.93,35.18 56.2,41.9 56.05,41.9 55.8,42.15 55.8,42.3 55.75,42.36 U17.1 55.75,44.34 v1(55.75,43.1) ; U15.D2 v1(63,38.24) ; R116.1 v1(55.1,43.1)
  BOTTOM w0.127: v1(62.93,33.85) 63,33.92 v1(63,38.24) ; v1(55.1,43.1) v1(55.75,43.1)
N30061775: length 21.5
  TOP w0.127: U17.2 v1(56.25,42.35) 56.25,42.33 64.93,33.66 v1(65.28,33.66) ; R117.1 v1(55.1,42.35) ; U13.D2 v1(65.25,38.24)
  BOTTOM w0.127: v1(65.28,33.66) 65.25,33.68 v1(65.25,38.24) ; v1(55.1,42.35) v1(56.25,42.35)
N30061790: length 25.9
  TOP w0.127: U11.D2 v1(67.5,38.24) ; v1(67.56,34.16) 64.87,34.16 56.7,42.33 v1(56.7,43.35) 56.7,44.3 U17.3 ; v1(59.35,41.65) 59.8,41.2 R118.1
  BOTTOM w0.127: v1(67.5,38.24) 67.5,34.22 v1(67.56,34.16) ; v1(59.35,41.65) 57.4,41.65 56.75,42.3 56.75,43.1 56.7,43.15 v1(56.7,43.35)
N30061799: length 25.2
  TOP w0.127: v1(69.72,34.67) 64.77,34.67 57.25,42.19 v1(57.25,42.6) U17.4 ; U9.D2 v1(69.75,38.24) ; v1(59.4,42.45) 59.4,42.3 59.8,41.9 R119.1
  BOTTOM w0.127: v1(59.4,42.45) 59.25,42.6 v1(57.25,42.6) ; v1(69.75,38.24) 69.75,34.7 v1(69.72,34.67)
N30061855: length 25.8
  TOP w0.127: U7.D2 v1(72,38.24) ; U17.5 v1(57.75,43.25) 58.1,42.9 58.1,41.73 64.67,35.16 v1(72.01,35.16) ; v1(59.4,43.25) 59.4,43.15 59.95,42.6 R120.1
  BOTTOM w0.127: v1(72,38.24) 72,35.16 v1(72.01,35.16) ; v1(59.4,43.25) v1(57.75,43.25)
N30061867: length 26.3
  TOP w0.127: U5.D2 v1(74.25,38.24) ; 58.55,43.57 58.68,43.7 59.75,43.7 R121.1 ; 58.55,43.57 58.25,43.87 U17.6 ; 58.55,43.57 58.55,41.71 64.6,35.66 72.93,35.66 73.15,35.43 v1(74.3,35.43)
  BOTTOM w0.127: v1(74.25,38.24) 74.25,35.48 v1(74.3,35.43)
N30061915: length 7.5
  TOP w0.127: U16.6 69,47.84 69.47,47.37 69.98,47.37 70.51,46.84 R18.2 70.75,46.78 72.9,44.63 72.9,44.1 U4.B2
N30061925: length 6.5
  TOP w0.127: U6.B2 70.48,44.26 70.48,44.83 69.98,45.34 69.98,46.61 69.8,46.78 R17.2 68.5,47.79 U16.5
N30061937: length 6.2
  TOP w0.127: U16.4 68,47.29 R16.2 68.79,46.78 68.96,46.61 68.96,45.34 68.45,44.83 68.45,44.05 U8.B2
N30061944: length 6.4
  TOP w0.127: U16.3 R15.2 67.23,46.78 67.01,46.56 67.01,45.29 66.8,45.09 66.42,45.09 66.17,44.83 66.17,44.08 U10.B2
N30061956: length 7.7
  TOP w0.127: U12.B2 63.96,44.04 63.96,44.68 64.34,45.06 65.76,45.06 66.04,45.34 66.04,46.61 66.21,46.78 R14.2 67,47.29 U16.2
N30061963: length 8.8
  TOP w0.127: U16.1 66.5,47.79 R13.2 63.04,46.78 61.72,45.47 61.72,44.03 U14.B2
N30062261: length 28.8
  TOP w0.127: U13.B1 64.41,39.75 v1(64.28,39.88) ; v1(71.03,39.88) 71.16,39.75 U7.B1 ; v1(68.78,39.88) 68.91,39.75 U9.B1 ; U15.B1 v1(61.99,39.75) ; U5.B1 73.41,39.75 v1(73.28,39.88) ; U11.B1 66.66,39.75 v1(66.53,39.88) ; R34.2 v1(82.03,41.28)
  TOP w0.23: R34.2 R12.2 82.08,42.8 Q7.6
  PWR_GND w0.3: v1(61.99,39.75) 62,39.75 62.35,40.1 63.45,40.1 63.67,39.88 v1(64.28,39.88) 65.13,39.88 65.25,40 66.41,40 v1(66.53,39.88) 67.38,39.88 67.5,40 68.66,40 v1(68.78,39.88) 68.98,39.88 69.19,40.09 70.21,40.09 70.42,39.88 v1(71.03,39.88) 71.73,39.88 71.85,40 73.16,40 v1(73.28,39.88) 73.57,39.88 75.2,38.25 79.6,38.25 82.03,40.68 v1(82.03,41.28)
N30066642: length 17.4
  TOP w0.127: U34.1 65.06,26.25 64.31,27 R20.2 64.03,26.72 63.88,26.57 63.65,26.57 63.64,26.57 62.7,26.57 62.6,26.47 61.09,26.47 57.79,23.16 57.79,17 U33.B2
N30066644: length 15.4
  TOP w0.127: U34.2 64.75,25.75 64.37,26.13 R21.2 64.03,25.76 63.91,25.63 62.62,25.63 62.55,25.69 61.3,25.69 60.2,24.59 60.2,16.87 U31.B2
N30066646: length 14.4
  TOP w0.127: U29.B2 62.87,17 62.87,18.16 60.73,20.29 60.73,23.39 62.08,24.74 62.62,24.74 62.7,24.82 63.88,24.82 64.03,24.97 R22.2 U34.3
N30066648: length 14
  TOP w0.127: U34.4 64.41,24.75 R23.2 64.03,24.1 63.86,23.93 62.7,23.93 62.68,23.95 62.2,23.95 61.52,23.27 61.52,21.67 65.28,17.91 65.28,16.87 U27.B2
N30066650: length 14
  TOP w0.127: U34.5 64.79,24.25 R24.2 64.03,23.28 63.91,23.15 62.79,23.15 62.44,22.8 62.44,21.51 66.17,17.78 67.56,17.78 67.82,17.53 67.82,16.87 U24.B2
N30066652: length 13.8
  TOP w0.127: U21.B2 70.36,16.87 70.36,17.65 69.8,18.21 66.6,18.21 64.03,20.78 R26.2 64.4,22.62 64.64,22.86 64.64,23.37 65.02,23.75 U34.6
N30067494: length 13.8
  TOP w0.127: U19.B2 72.9,16.87 72.9,17.91 72.14,18.67 67.18,18.67 66.04,19.81 66.04,21.44 65.94,21.53 R28.2 65.62,21.81 66.25,22.44 U34.7
N30068975: length 15.9
  TOP w0.127: U32.B2 75.56,17 75.56,18.42 74.93,19.05 67.41,19.05 66.98,19.48 66.98,21.29 66.73,21.53 R33.2 66.5,21.98 66.75,22.23 U34.8
N30069156: length 17.8
  TOP w0.127: U30.B2 79.5,16.87 79.5,17.53 77.57,19.46 68.68,19.46 68.02,20.12 68.02,21.13 67.62,21.53 R32.2 67.5,22.23 67.75,22.48 U34.10
N30069185: length 19.2
  TOP w0.127: U34.11 68.25,21.79 R31.2 68.81,21.53 69.04,21.31 69.04,20.17 69.39,19.81 77.85,19.81 79.98,17.68 81.76,17.68 81.92,17.53 81.92,16.74 U28.B2
N30069197: length 20.3
  TOP w0.127: U34.12 68.75,22.29 R30.2 70.29,21.53 71.63,20.19 78.11,20.19 80.36,17.93 84.05,17.93 84.45,17.53 84.45,16.74 U26.B2
N30069235: length 22.8
  TOP w0.127: U34.13 70.34,23.75 R29.2 70.97,21.62 72.01,20.57 78.36,20.57 80.75,18.19 86.26,18.19 87.02,17.43 87.02,16.77 U23.B2
N30069271: length 24.8
  TOP w0.127: U34.14 70.72,24.25 R27.2 70.97,23.78 71.25,23.5 72.39,23.5 74.8,21.08 78.41,21.08 81.05,18.44 86.51,18.44 87.4,17.55 89.37,17.55 89.51,17.41 89.51,17.4 89.56,17.35 89.56,16.77 U20.B2
N30069280: length 28
  TOP w0.127: U18.B2 92.2,16.87 92.2,17.55 91.95,17.81 87.53,17.81 86.54,18.8 81.18,18.8 78.51,21.46 75.24,21.46 72.8,23.9 72.8,24.1 72.42,24.49 71.09,24.49 70.97,24.61 R25.2 70.51,24.88 70.38,24.75 U34.15
N30070866: length 37.8
  TOP w0.127: v1(103.52,36.05) 103.25,36.32 U22.A1 ; U23.C1 85.78,15.07 v1(85.53,14.83)
  BOTTOM w0.127: v1(85.53,14.83) 86.9,13.46 92.17,13.46 102.01,23.3 102.01,27.71 100.84,28.88 100.84,34.54 101.85,35.56 103.03,35.56 v1(103.52,36.05)
N30070870: length 36.7
  TOP w0.127: U25.A1 103.25,32.07 v1(103.52,31.8) ; U26.C1 83.24,15.07 v1(82.99,14.83)
  BOTTOM w0.127: v1(82.99,14.83) 84.74,13.08 92.33,13.08 102.39,23.14 102.39,28.09 101.37,29.11 101.37,29.79 101.75,30.18 103.23,30.18 103.52,30.47 v1(103.52,31.8)
N30103916: length 13.7
  TOP w0.127: v1(91.97,40.73) 92.71,40 R72.1
  BOTTOM w0.127: J8.2 90.32,49.11 90.32,46.16 91.97,44.51 v1(91.97,40.73)
N30104433: length 2.9
  TOP w0.127: U3.24 95,39.25 C46.1 94.72,39.47 R73.2 R72.2
N30112835: length 1.1
  TOP w0.3: U36.2 R38.1
N30116209: length 55.1
  TOP w0.127: U39.19 83.75,28 R51.1 85.35,28.5 v1(85.37,28.48) ; Q6.3 v1(85.38,31.46) ; v1(85.37,31.46) 84.57,31.46 83.75,30.63 65.12,30.63 62.97,32.79 62.79,32.79 61.68,33.9 61.68,35.54 55.92,41.3 55.85,41.3 55.75,41.4 53.55,41.4 51.3,43.65 51.3,46.9 51.9,47.5 U17.19
  BOTTOM w0.127: v1(85.37,28.48) v1(85.37,31.46) v1(85.38,31.46)
N30116224: length 49.8
  TOP w0.127: v1(83.97,29.62) 83.88,29.52 83.88,28.76 83.62,28.5 R50.1 83.25,28.25 U39.20 ; U17.20 51.9,47 51.6,46.7 51.6,43.75 53.65,41.7 55.85,41.7 55.95,41.6 56.04,41.6 62.19,35.46 62.19,33.95 64.67,31.46 Q5.3 83.22,31.46 83.28,31.52 v1(83.85,31.52)
  BOTTOM w0.127: v1(83.97,29.62) 83.97,31.4 v1(83.85,31.52)
N30125838: length 0.9
  TOP w0.127: U2.30 106.76,5.12 R7.1
N30125857: length 0.9
  TOP w0.127: U2.2 108.76,2.66 R9.1
N30126826: length 1.6
  TOP w0.3: R47.1 SW1UI3.2
N30126876: length 9.6
  TOP w0.2: 17.69,15.1 17.7,15.09 J7.2 ; J7.6 18.5,15.13 18.39,15.24 ; J7.4 18.1,15.09 18.09,15.09
  TOP w0.203: J7.6 18.5,14.1 18.51,14.09 18.51,13.45 18.71,13.25 19.89,13.25 20.09,13.45 20.09,14.09 20.1,14.1 J7.14
  TOP w0.381: 6.59,36.91 J10.1 ; J10.1 7.5,36 ; J10.1 7.5,37.82
  TOP w0.5: 8.41,36.91 J10.1
N30126894: length 3.7
  TOP w0.381: J14.1 14.66,36.91 ; J14.1 12.84,36.91 ; J14.1 13.75,37.82 ; J14.1 13.75,36
N30126899: length 7.8
  TOP w0.2: v1(19.94,15.37) 19.7,15.13 J7.12
  TOP w0.5: R82.2 20.84,37.75 J15.1
  PWR_GND w0.381: J15.1 20,37.82 ; J15.1 19.09,36.91 ; J15.1 20.91,36.91 ; J15.1 20,36
  vias: v1(20.32,20.45)
N30153200: length 52.4
  TOP w0.127: v1(71.75,26.67) 70.84,25.75 U34.17 ; R110.2 105.1,38.28 v1(104.39,38.99) 104.27,38.86 104.27,34.93 104.14,34.8 103.25,34.8 102.75,34.3 102.75,34
  BOTTOM w0.127: v1(71.75,26.67) 75.08,30 77.5,30 80.67,33.17 89.05,33.17 91.21,35.33 91.21,39.52 91.72,40.03 97.06,40.03 97.82,40.79 97.82,41.18 98.07,41.43 101.95,41.43 v1(104.39,38.99)
N30154037: length 1.8
  TOP w0.127: U17.10 59.64,46.5 60.14,46 R52.1
N30154081: length 1.7
  TOP w0.127: U17.11 59.85,47 60.1,46.75 R53.1
N30154121: length 1.6
  TOP w0.127: R54.1 U17.12
N30154162: length 1.6
  TOP w0.127: U17.13 R55.1
N30154204: length 1.7
  TOP w0.127: R56.1 57.75,49.5 U17.14
N30154247: length 1.8
  TOP w0.127: R57.1 57.25,49.25 U17.15
N30156263: length 1.7
  TOP w0.127: R58.1 82.75,21.75 U39.10
N30156279: length 1.6
  TOP w0.127: U39.11 R59.1
N30156284: length 1.7
  TOP w0.127: R60.1 83.75,21.75 U39.12
N30156311: length 1.6
  TOP w0.127: U39.13 85.25,23.75 R61.1
N30156316: length 1.4
  TOP w0.127: R62.1 85.5,24.25 U39.14
N30156332: length 1.3
  TOP w0.127: U39.15 R63.1
N30156954: length 2.3
  TOP w0.127: R64.1 79,26.75 79.5,26.25 U39.1
N30156970: length 2.2
  TOP w0.127: R65.1 79.12,26 79.38,25.75 U39.2
N30156975: length 2.1
  TOP w0.127: U39.3 R66.1
N30157002: length 2.2
  TOP w0.127: U39.4 79.76,24.75 79.51,24.5 R67.1
N30157007: length 2.3
  TOP w0.127: R68.1 79.38,23.75 79.88,24.25 U39.5
N30157023: length 2.4
  TOP w0.127: R69.1 79.13,23 79.88,23.75 U39.6
N30157147: length 13.1
  TOP w0.127: R70.1 v1(72.9,14.39) ; U39.7 81.25,22.83 v1(80.64,22.23)
  BOTTOM w0.127: v1(80.64,22.23) 73.79,15.37 73.28,15.37 72.9,14.99 v1(72.9,14.39)
N30157152: length 10.2
  TOP w0.127: U39.8 81.75,22.39 v1(81.92,22.23) ; R71.1 v1(76.22,15.98)
  BOTTOM w0.127: v1(81.92,22.23) 76.22,16.54 v1(76.22,15.98)
N30158305: length 2.7
  TOP w0.127: U3.13 98.86,35 99.06,34.8 99.8,34.8 R74.1 99.98,35.02 C40.1
N30158329: length 3.9
  TOP w0.127: U3.12 97.5,33.86 97.86,33.5 99.25,33.5 99.5,33.25 R75.1 100.23,32.75 C41.1
